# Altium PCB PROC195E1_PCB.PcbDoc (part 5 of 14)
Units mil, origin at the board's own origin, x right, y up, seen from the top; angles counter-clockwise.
Board outline 3110.24 x 2500 mil, 10 copper layers (Top Layer, L02_GND1, L03_SIG1, L04_GND2, L05_PWR1, L06_PWR2, L07_GND3, L08_SIG2, L09_GND4, Bottom Layer), stack 66.407 mil thick; 571 components, 538 nets, 6726 pads, 1286 vias.
Unrouted connection lines stored in the file: 4.
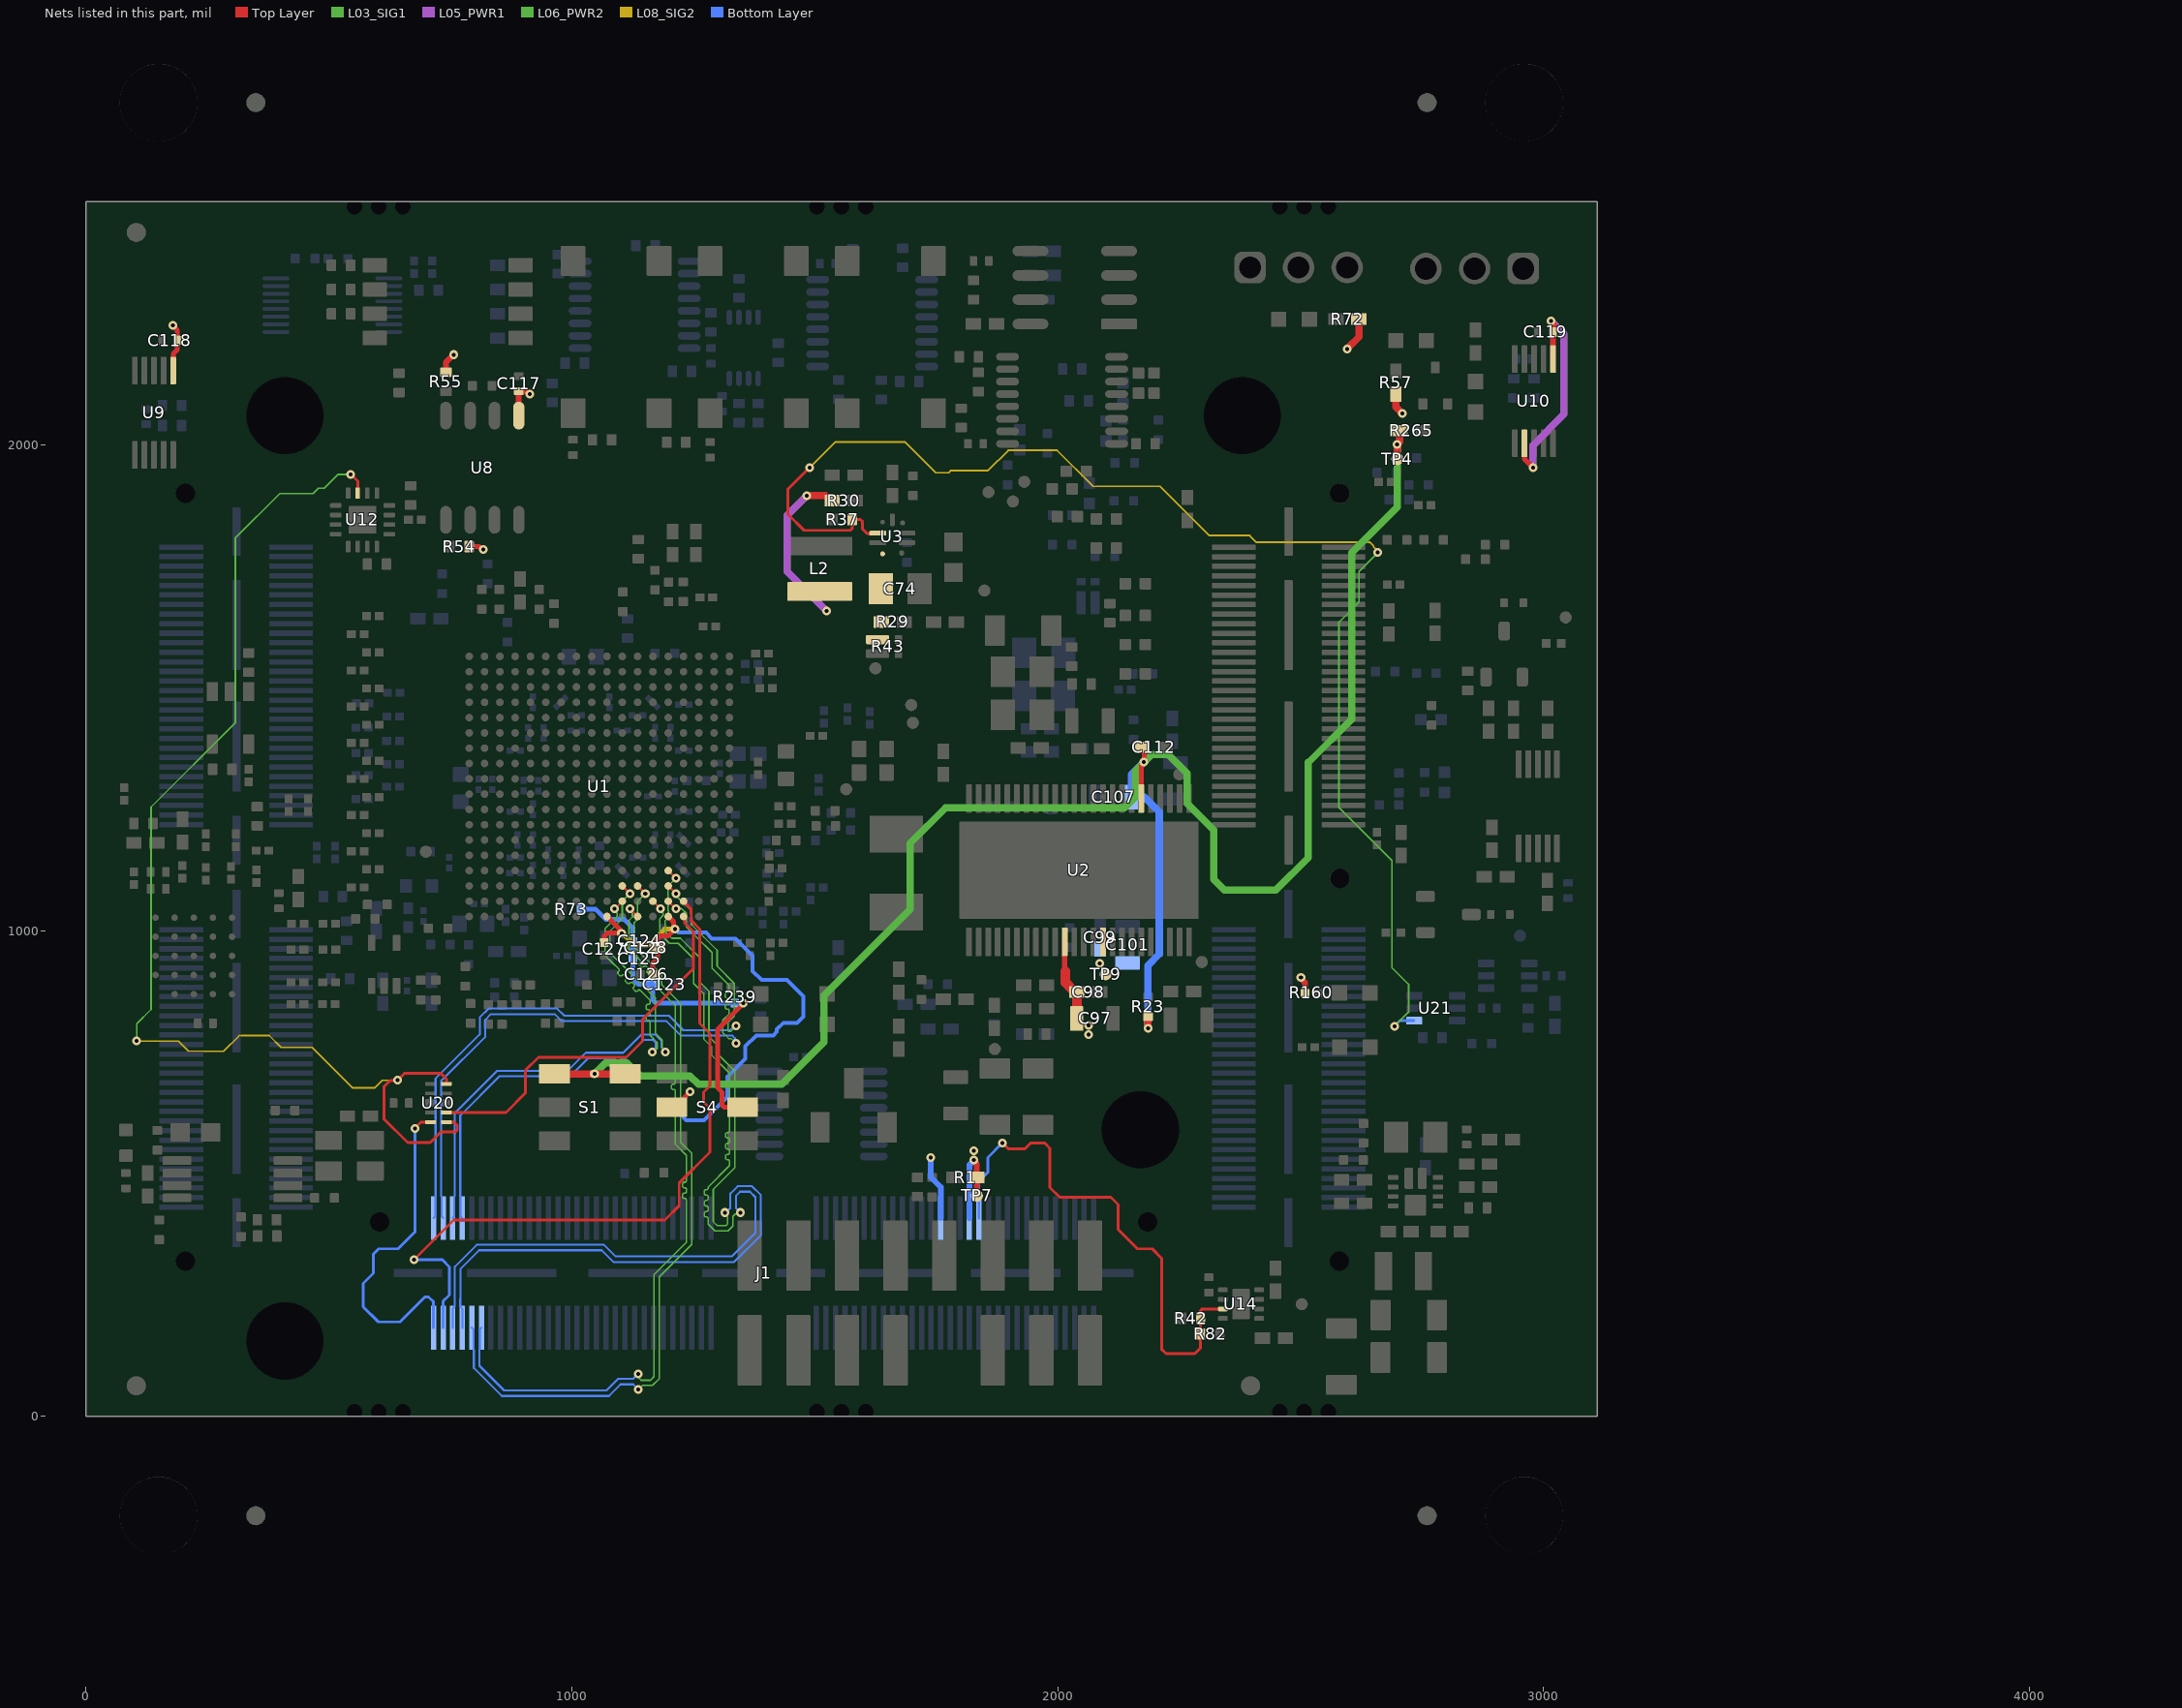
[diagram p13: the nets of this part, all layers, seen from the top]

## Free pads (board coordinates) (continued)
  round 2.5 on Mech16: 1(2331.73,1000.23) 1(2331.73,1006.23) 1(2331.73,1216.72) 1(2331.73,1222.72) 1(2331.73,1236.41) 1(2331.73,1242.41) 1(2331.73,1256.1) 1(2331.73,1262.1) 1(2331.73,1275.79) 1(2331.73,1281.79) 1(2331.73,1295.48) 1(2331.73,1301.48) 1(2331.73,1315.17) 1(2331.73,1321.17) 1(2331.73,1334.86) 1(2331.73,1340.86) 1(2331.73,1354.55) 1(2331.73,1360.55) 1(2331.73,1374.24) 1(2331.73,1380.24) 1(2331.73,1393.93) 1(2331.73,1399.93) 1(2331.73,1413.62) 1(2331.73,1419.62) 1(2331.73,1433.31) 1(2331.73,1439.31) 1(2331.73,1453) 1(2331.73,1459) 1(2331.73,1472.69) 1(2331.73,1478.69) 1(2331.73,1492.38) 1(2331.73,1498.38) 1(2331.73,1512.07) 1(2331.73,1518.07) 1(2331.73,1531.76) 1(2331.73,1537.76) 1(2331.73,1551.45) 1(2331.73,1557.45) 1(2331.73,1571.14) 1(2331.73,1577.14) 1(2331.73,1590.83) 1(2331.73,1596.83) 1(2331.73,1610.47) 1(2331.73,1610.52) 1(2331.73,1616.47) 1(2331.73,1616.52) 1(2331.73,1630.21) 1(2331.73,1636.21) 1(2331.73,1649.9) 1(2331.73,1655.9) 1(2331.73,1669.59) 1(2331.73,1675.59) 1(2331.73,1689.28) 1(2331.73,1695.28) 1(2331.73,1708.97) 1(2331.73,1714.97) 1(2331.73,1728.66) 1(2331.73,1734.66) 1(2331.73,1748.35) 1(2331.73,1754.35) 1(2331.73,1768.04) 1(2331.73,1774.04) 1(2331.73,1787.73) 1(2331.73,1793.73) 1(2331.73,1923.98) 1(2331.73,1923.98) 1(2345.96,314.7) 1(2345.96,314.7) 1(2345.96,314.7) 1(2345.96,1908.25) 1(2345.96,1908.25) 1(2345.96,1908.25) 1(2351.73,320.48) 1(2351.73,320.48) 1(2351.73,320.48) 1(2351.73,1902.48) 1(2351.73,1902.48) 1(2351.73,1902.48) 1(2541.73,320.48) 1(2541.73,320.48) 1(2541.73,320.48) 1(2541.73,1902.48) 1(2541.73,1902.48) 1(2541.73,1902.48) 1(2544.12,314.7) 1(2544.12,314.7) 1(2544.12,314.7) 1(2544.12,1908.25) 1(2544.12,1908.25) 1(2544.12,1908.25) 1(2547.71,306.98) 1(2547.71,306.98) 1(2596.73,375.48) 1(2596.73,375.48) 1(2596.73,375.48) 1(2596.73,1847.48) 1(2596.73,1847.48) 1(2596.73,1847.48) 1(2602.51,373.08) 1(2602.51,373.08) 1(2602.51,373.08) 1(2602.51,1849.87) 1(2602.51,1849.87) 1(2602.51,1849.87) 1(2608.73,306.98) 1(2608.73,306.98) 1(2608.73,368) 1(2608.73,368) 1(2616.73,298.98) 1(2616.73,298.98) 1(2616.73,429.22) 1(2616.73,435.22) 1(2616.73,448.91) 1(2616.73,454.91) 1(2616.73,468.6) 1(2616.73,474.6) 1(2616.73,488.29) 1(2616.73,494.29) 1(2616.73,507.98) 1(2616.73,513.98) 1(2616.73,527.67) 1(2616.73,533.67) 1(2616.73,547.36) 1(2616.73,553.36) 1(2616.73,567.05) 1(2616.73,573.05) 1(2616.73,586.74) 1(2616.73,592.74) 1(2616.73,606.43) 1(2616.73,612.43) 1(2616.73,626.12) 1(2616.73,632.12) 1(2616.73,645.81) 1(2616.73,651.81) 1(2616.73,665.5) 1(2616.73,671.5) 1(2616.73,685.19) 1(2616.73,691.19) 1(2616.73,704.88) 1(2616.73,710.88) 1(2616.73,724.57) 1(2616.73,730.57) 1(2616.73,744.26) 1(2616.73,750.26) 1(2616.73,763.95) 1(2616.73,769.95) 1(2616.73,783.64) 1(2616.73,789.64) 1(2616.73,803.33) 1(2616.73,809.33) 1(2616.73,823.02) 1(2616.73,829.02) 1(2616.73,842.71) 1(2616.73,848.71) 1(2616.73,862.4) 1(2616.73,868.4) 1(2616.73,882.09) 1(2616.73,888.09) 1(2616.73,901.78) 1(2616.73,907.78) 1(2616.73,921.47) 1(2616.73,927.47) 1(2616.73,941.16) 1(2616.73,947.16) 1(2616.73,960.85) 1(2616.73,966.85) 1(2616.73,980.54) 1(2616.73,986.54) 1(2616.73,1000.23) 1(2616.73,1006.23) 1(2616.73,1216.72) 1(2616.73,1222.72) 1(2616.73,1236.41) 1(2616.73,1242.41) 1(2616.73,1256.1) 1(2616.73,1262.1) 1(2616.73,1275.79) 1(2616.73,1281.79) 1(2616.73,1295.48) 1(2616.73,1301.48) 1(2616.73,1315.17) 1(2616.73,1321.17) 1(2616.73,1334.86) 1(2616.73,1340.86) 1(2616.73,1354.55) 1(2616.73,1360.55) 1(2616.73,1374.24) 1(2616.73,1380.24) 1(2616.73,1393.93) 1(2616.73,1399.93) 1(2616.73,1413.62) 1(2616.73,1419.62) 1(2616.73,1433.31) 1(2616.73,1439.31) 1(2616.73,1453) 1(2616.73,1459) 1(2616.73,1472.69) 1(2616.73,1478.69) 1(2616.73,1492.38) 1(2616.73,1498.38) 1(2616.73,1512.07) 1(2616.73,1518.07) 1(2616.73,1531.76) 1(2616.73,1537.76) 1(2616.73,1551.45) 1(2616.73,1557.45) 1(2616.73,1571.14) 1(2616.73,1577.14) 1(2616.73,1590.83) 1(2616.73,1596.83) 1(2616.73,1610.47) 1(2616.73,1610.52) 1(2616.73,1616.47) 1(2616.73,1616.52) 1(2616.73,1630.21) 1(2616.73,1636.21) 1(2616.73,1649.9) 1(2616.73,1655.9) 1(2616.73,1669.59) 1(2616.73,1675.59) 1(2616.73,1689.28) 1(2616.73,1695.28) 1(2616.73,1708.97) 1(2616.73,1714.97) 1(2616.73,1728.66) 1(2616.73,1734.66) 1(2616.73,1748.35) 1(2616.73,1754.35) 1(2616.73,1768.04) 1(2616.73,1774.04) 1(2616.73,1787.73) 1(2616.73,1793.73) 1(2616.73,1923.98) 1(2616.73,1923.98) 1(2621.73,429.22) 1(2621.73,429.22) 1(2621.73,435.22) 1(2621.73,435.22) 1(2621.73,448.91) 1(2621.73,448.91) 1(2621.73,454.91) 1(2621.73,454.91) 1(2621.73,468.6) 1(2621.73,468.6) 1(2621.73,474.6) 1(2621.73,474.6) 1(2621.73,488.29) 1(2621.73,488.29) 1(2621.73,494.29) 1(2621.73,494.29) 1(2621.73,507.98) 1(2621.73,507.98) 1(2621.73,513.98) 1(2621.73,513.98) 1(2621.73,527.67) 1(2621.73,527.67) 1(2621.73,533.67) 1(2621.73,533.67) 1(2621.73,547.36) 1(2621.73,547.36) 1(2621.73,553.36) 1(2621.73,553.36) 1(2621.73,567.05) 1(2621.73,567.05) 1(2621.73,573.05) 1(2621.73,573.05) 1(2621.73,586.74) 1(2621.73,586.74) 1(2621.73,592.74) 1(2621.73,592.74) 1(2621.73,606.43) 1(2621.73,606.43) 1(2621.73,612.43) 1(2621.73,612.43) 1(2621.73,626.12) 1(2621.73,626.12) 1(2621.73,632.12) 1(2621.73,632.12) 1(2621.73,645.81) 1(2621.73,645.81) 1(2621.73,651.81) 1(2621.73,651.81) 1(2621.73,665.5) 1(2621.73,665.5) 1(2621.73,671.5) 1(2621.73,671.5) 1(2621.73,685.19) 1(2621.73,685.19) 1(2621.73,691.19) 1(2621.73,691.19) 1(2621.73,704.88) 1(2621.73,704.88) 1(2621.73,710.88) 1(2621.73,710.88) 1(2621.73,724.57) 1(2621.73,724.57) 1(2621.73,730.57) 1(2621.73,730.57) 1(2621.73,744.26) 1(2621.73,744.26) 1(2621.73,750.26) 1(2621.73,750.26) 1(2621.73,763.95) 1(2621.73,763.95) 1(2621.73,769.95) 1(2621.73,769.95) 1(2621.73,783.64) 1(2621.73,783.64) 1(2621.73,789.64) 1(2621.73,789.64) 1(2621.73,803.33) 1(2621.73,803.33) 1(2621.73,809.33) 1(2621.73,809.33) 1(2621.73,823.02) 1(2621.73,823.02) 1(2621.73,829.02) 1(2621.73,829.02) 1(2621.73,842.71) 1(2621.73,842.71) 1(2621.73,848.71) 1(2621.73,848.71) 1(2621.73,862.4) 1(2621.73,862.4) 1(2621.73,868.4) 1(2621.73,868.4) 1(2621.73,882.09) 1(2621.73,882.09) 1(2621.73,888.09) 1(2621.73,888.09) 1(2621.73,901.78) 1(2621.73,901.78) 1(2621.73,907.78) 1(2621.73,907.78) 1(2621.73,921.47) 1(2621.73,921.47) 1(2621.73,927.47) 1(2621.73,927.47) 1(2621.73,941.16) 1(2621.73,941.16) 1(2621.73,947.16) 1(2621.73,947.16) 1(2621.73,960.85) 1(2621.73,960.85) 1(2621.73,966.85) 1(2621.73,966.85) 1(2621.73,980.54) 1(2621.73,980.54) 1(2621.73,986.54) 1(2621.73,986.54) 1(2621.73,1000.23) 1(2621.73,1000.23) 1(2621.73,1006.23) 1(2621.73,1006.23) 1(2621.73,1216.72) 1(2621.73,1216.72) 1(2621.73,1222.72) 1(2621.73,1222.72) 1(2621.73,1236.41) 1(2621.73,1236.41) 1(2621.73,1242.41) 1(2621.73,1242.41) 1(2621.73,1256.1) 1(2621.73,1256.1) 1(2621.73,1262.1) 1(2621.73,1262.1) 1(2621.73,1275.79) 1(2621.73,1275.79) 1(2621.73,1281.79) 1(2621.73,1281.79) 1(2621.73,1295.48) 1(2621.73,1295.48) 1(2621.73,1301.48) 1(2621.73,1301.48) 1(2621.73,1315.17) 1(2621.73,1315.17) 1(2621.73,1321.17) 1(2621.73,1321.17) 1(2621.73,1334.86) 1(2621.73,1334.86) 1(2621.73,1340.86) 1(2621.73,1340.86) 1(2621.73,1354.55) 1(2621.73,1354.55) 1(2621.73,1360.55) 1(2621.73,1360.55) 1(2621.73,1374.24) 1(2621.73,1374.24) 1(2621.73,1380.24) 1(2621.73,1380.24) 1(2621.73,1393.93) 1(2621.73,1393.93) 1(2621.73,1399.93) 1(2621.73,1399.93) 1(2621.73,1413.62) 1(2621.73,1413.62) 1(2621.73,1419.62) 1(2621.73,1419.62) 1(2621.73,1433.31) 1(2621.73,1433.31) 1(2621.73,1439.31) 1(2621.73,1439.31) 1(2621.73,1453) 1(2621.73,1453) 1(2621.73,1459) 1(2621.73,1459) 1(2621.73,1472.69) 1(2621.73,1472.69) 1(2621.73,1478.69) 1(2621.73,1478.69) 1(2621.73,1492.38) 1(2621.73,1492.38) 1(2621.73,1498.38) 1(2621.73,1498.38) 1(2621.73,1512.07) 1(2621.73,1512.07) 1(2621.73,1518.07) 1(2621.73,1518.07) 1(2621.73,1531.76) 1(2621.73,1531.76) 1(2621.73,1537.76) 1(2621.73,1537.76) 1(2621.73,1551.45) 1(2621.73,1551.45) 1(2621.73,1557.45) 1(2621.73,1557.45) 1(2621.73,1571.14) 1(2621.73,1571.14) 1(2621.73,1577.14) 1(2621.73,1577.14) 1(2621.73,1590.83) 1(2621.73,1590.83) 1(2621.73,1596.83) 1(2621.73,1596.83) 1(2621.73,1610.47) 1(2621.73,1610.47) 1(2621.73,1610.52) 1(2621.73,1610.52) 1(2621.73,1616.47) 1(2621.73,1616.47) 1(2621.73,1616.52) 1(2621.73,1616.52) 1(2621.73,1630.21) 1(2621.73,1630.21) 1(2621.73,1636.21) 1(2621.73,1636.21) 1(2621.73,1649.9) 1(2621.73,1649.9) 1(2621.73,1655.9) 1(2621.73,1655.9) 1(2621.73,1669.59) 1(2621.73,1669.59) 1(2621.73,1675.59) 1(2621.73,1675.59) 1(2621.73,1689.28) 1(2621.73,1689.28) 1(2621.73,1695.28) 1(2621.73,1695.28) 1(2621.73,1708.97) 1(2621.73,1708.97) 1(2621.73,1714.97) 1(2621.73,1714.97) 1(2621.73,1728.66) 1(2621.73,1728.66) 1(2621.73,1734.66) 1(2621.73,1734.66) 1(2621.73,1748.35) 1(2621.73,1748.35) 1(2621.73,1754.35) 1(2621.73,1754.35) 1(2621.73,1768.04) 1(2621.73,1768.04) 1(2621.73,1774.04) 1(2621.73,1774.04) 1(2621.73,1787.73) 1(2621.73,1787.73) 1(2621.73,1793.73) 1(2621.73,1793.73)
  round 3.94 on Mech16: 1(192.48,1023.39) 1(192.48,1196.61) 1(192.68,367.32) 1(192.68,367.32) 1(192.68,409.21) 1(192.68,1810.79) 1(192.68,1852.68) 1(192.68,1852.68) 1(237.52,322.48) 1(237.52,322.48) 1(237.52,1897.52) 1(237.52,1897.52) 1(364.13,322.48) 1(364.13,1897.52) 1(427.32,1810.79) 1(427.32,1897.6) 1(427.52,323.19) 1(427.52,410) 1(427.52,1023.39) 1(427.52,1196.61) 1(513.9,-174.26) 1(513.9,-174.26) 1(513.9,-144.74) 1(513.9,-114.22) 1(513.9,-102.41) 1(519.81,-174.26) 1(592.64,-169.34) 1(592.64,-157.53) 1(592.64,-114.22) 1(592.64,-102.41) 1(607.48,240.87) 1(607.48,367.48) 1(607.48,367.48) 1(607.48,1865.87) 1(607.48,1992.48) 1(607.48,1992.48) 1(608.19,177.48) 1(608.19,1802.48) 1(652.32,412.32) 1(652.32,412.32) 1(652.32,2037.32) 1(652.32,2037.32) 1(694.21,412.32) 1(694.21,2037.32) 1(695,177.48) 1(695,1802.48) 1(735.63,-173.39) 1(735.63,-173.39) 1(735.63,-143.86) 1(735.63,-113.35) 1(735.63,-101.53) 1(741.54,-173.39) 1(814.37,-168.46) 1(814.37,-156.65) 1(814.37,-113.35) 1(814.37,-101.53) 1(969.98,-176.52) 1(969.98,-176.52) 1(969.98,-146.99) 1(969.98,-116.48) 1(969.98,-104.67) 1(975.88,-176.52) 1(1048.72,-171.6) 1(1048.72,-159.79) 1(1048.72,-116.48) 1(1048.72,-104.67) 1(1308.39,177.48) 1(1308.39,412.52) 1(1308.39,1802.48) 1(1308.39,2037.52) 1(1481.61,177.48) 1(1481.61,412.52) 1(1481.61,1802.48) 1(1481.61,2037.52) 1(2095.79,177.68) 1(2095.79,412.32) 1(2095.79,1802.68) 1(2095.79,2037.32) 1(2126.37,75) 1(2137.68,412.32) 1(2137.68,412.32) 1(2137.68,2037.32) 1(2137.68,2037.32) 1(2182.52,240.87) 1(2182.52,367.48) 1(2182.52,367.48) 1(2182.52,1865.87) 1(2182.52,1992.48) 1(2182.52,1992.48) 1(2182.6,177.68) 1(2182.6,1802.68) 1(2233.63,75) 1(2357.48,1023.39) 1(2357.48,1196.61) 1(2357.48,1810) 1(2357.48,1896.81) 1(2357.68,322.4) 1(2357.68,409.21) 1(2366.37,-15) 1(2386.37,175) 1(2420.87,322.48) 1(2420.87,1897.52) 1(2473.63,-15) 1(2493.63,175) 1(2547.48,322.48) 1(2547.48,322.48) 1(2547.48,1897.52) 1(2547.48,1897.52) 1(2592.32,367.32) 1(2592.32,367.32) 1(2592.32,409.21) 1(2592.32,1810.79) 1(2592.32,1852.68) 1(2592.32,1852.68) 1(2592.52,1023.39) 1(2592.52,1196.61) 1(2835.35,1078.35) 1(2835.35,1121.65) 1(2835.35,1128.35) 1(2835.35,1171.65) 1(2906.21,1078.35) 1(2906.21,1121.65) 1(2906.21,1128.35) 1(2906.21,1171.65) 1(3027.15,606.09) 1(3027.15,610.81) 1(3027.15,610.81) 1(3027.15,1559.37) 1(3027.15,1564.09) 1(3027.15,1564.09) 1(3032.07,610.81) 1(3032.07,610.81) 1(3032.07,1564.09) 1(3032.07,1564.09) 1(3037.98,496.64) 1(3037.98,1449.92) 1(3069.48,496.64) 1(3069.48,1449.92) 1(3075.38,610.81) 1(3075.38,1564.09) 1(3481.37,1020) 1(3588.63,1020)
  round 3.5 on Mech16: 1(293.38,-174.89) 1(293.38,-174.89) 1(293.38,-133.89) 1(293.38,-133.89) 1(316.38,-174.89) 1(316.38,-133.89) 1(323.35,-108) 1(323.35,-108) 1(323.35,-85) 1(323.35,-35) 1(323.35,-12) 1(323.35,-12) 1(364.35,-108) 1(364.35,-108) 1(364.35,-85) 1(364.35,-35) 1(364.35,-12) 1(364.35,-12) 1(366.38,-174.89) 1(366.38,-133.89) 1(384.5,-108) 1(384.5,-108) 1(384.5,-85) 1(384.5,-35) 1(384.5,-12) 1(384.5,-12) 1(389.38,-174.89) 1(389.38,-174.89) 1(389.38,-133.89) 1(389.38,-133.89) 1(413.38,-180.5) 1(413.38,-180.5) 1(413.38,-139.5) 1(413.38,-139.5) 1(425.5,-108) 1(425.5,-108) 1(425.5,-85) 1(425.5,-35) 1(425.5,-12) 1(425.5,-12) 1(436.38,-180.5) 1(436.38,-139.5) 1(486.38,-180.5) 1(486.38,-139.5) 1(486.39,575.77) 1(486.39,575.77) 1(486.39,601.75) 1(486.39,669.75) 1(486.39,695.73) 1(486.39,695.73) 1(509.38,-180.5) 1(509.38,-180.5) 1(509.38,-139.5) 1(509.38,-139.5) 1(518.35,-29.69) 1(518.35,-29.69) 1(518.35,-6.69) 1(518.35,43.31) 1(518.35,66.31) 1(518.35,66.31) 1(540.86,575.77) 1(540.86,575.77) 1(540.86,601.75) 1(540.86,669.75) 1(540.86,695.73) 1(540.86,695.73) 1(553.35,575.77) 1(553.35,575.77) 1(553.35,601.75) 1(553.35,669.75) 1(553.35,695.73) 1(553.35,695.73) 1(559.35,-29.69) 1(559.35,-29.69) 1(559.35,-6.69) 1(559.35,43.31) 1(559.35,66.31) 1(559.35,66.31) 1(579.5,-29.69) 1(579.5,-29.69) 1(579.5,-6.69) 1(579.5,43.31) 1(579.5,66.31) 1(579.5,66.31) 1(607.82,575.77) 1(607.82,575.77) 1(607.82,601.75) 1(607.82,669.75) 1(607.82,695.73) 1(607.82,695.73) 1(618.02,-175.32) 1(618.02,-175.32) 1(618.02,-134.32) 1(618.02,-134.32) 1(620.5,-29.69) 1(620.5,-29.69) 1(620.5,-6.69) 1(620.5,43.31) 1(620.5,66.31) 1(620.5,66.31) 1(620.73,575.77) 1(620.73,575.77) 1(620.73,601.75) 1(620.73,669.75) 1(620.73,695.73) 1(620.73,695.73) 1(641.02,-175.32) 1(641.02,-134.32) 1(657.05,-42.68) 1(657.05,-42.68) 1(657.05,-19.68) 1(657.05,30.32) 1(657.05,53.32) 1(657.05,53.32) 1(675.19,575.77) 1(675.19,575.77) 1(675.19,601.75) 1(675.19,669.75) 1(675.19,695.73) 1(675.19,695.73) 1(688.17,575.77) 1(688.17,575.77) 1(688.17,601.75) 1(688.17,669.75) 1(688.17,695.73) 1(688.17,695.73) 1(691.02,-175.32) 1(691.02,-134.32) 1(698.05,-42.68) 1(698.05,-42.68) 1(698.05,-19.68) 1(698.05,30.32) 1(698.05,53.32) 1(698.05,53.32) 1(714.02,-175.32) 1(714.02,-175.32) 1(714.02,-134.32) 1(714.02,-134.32) 1(718.2,-42.68) 1(718.2,-42.68) 1(718.2,-19.68) 1(718.2,30.32) 1(718.2,53.32) 1(718.2,53.32) 1(742.64,575.77) 1(742.64,575.77) 1(742.64,601.75) 1(742.64,669.75) 1(742.64,695.73) 1(742.64,695.73) 1(755.61,575.77) 1(755.61,575.77) 1(755.61,601.75) 1(755.61,669.75) 1(755.61,695.73) 1(755.61,695.73) 1(759.2,-42.68) 1(759.2,-42.68) 1(759.2,-19.68) 1(759.2,30.32) 1(759.2,53.32) 1(759.2,53.32) 1(810.08,575.77) 1(810.08,575.77) 1(810.08,601.75) 1(810.08,669.75) 1(810.08,695.73) 1(810.08,695.73) 1(823.05,575.77) 1(823.05,575.77) 1(823.05,601.75) 1(823.05,669.75) 1(823.05,695.73) 1(823.05,695.73) 1(838.35,-32.53) 1(838.35,-32.53) 1(838.35,-9.53) 1(838.35,40.47) 1(838.35,63.47) 1(838.35,63.47) 1(877.52,575.77) 1(877.52,575.77) 1(877.52,601.75) 1(877.52,669.75) 1(877.52,695.73) 1(877.52,695.73) 1(879.35,-32.53) 1(879.35,-32.53) 1(879.35,-9.53) 1(879.35,40.47) 1(879.35,63.47) 1(879.35,63.47) 1(890.5,575.77) 1(890.5,575.77) 1(890.5,601.75) 1(890.5,669.75) 1(890.5,695.73) 1(890.5,695.73) 1(899.5,-32.53) 1(899.5,-32.53) 1(899.5,-9.53) 1(899.5,40.47) 1(899.5,63.47) 1(899.5,63.47) 1(920.91,-180.47) 1(920.91,-180.47) 1(920.91,-157.47) 1(920.91,-107.47) 1(920.91,-84.47) 1(920.91,-84.47) 1(940.5,-32.53) 1(940.5,-32.53) 1(940.5,-9.53) 1(940.5,40.47) 1(940.5,63.47) 1(940.5,63.47) 1(944.96,575.77) 1(944.96,575.77) 1(944.96,601.75) 1(944.96,669.75) 1(944.96,695.73) 1(944.96,695.73) 1(957.94,575.77) 1(957.94,575.77) 1(957.94,601.75) 1(957.94,669.75) 1(957.94,695.73) 1(957.94,695.73) 1(961.91,-180.47) 1(961.91,-180.47) 1(961.91,-157.47) 1(961.91,-107.47) 1(961.91,-84.47) 1(961.91,-84.47) 1(1012.4,575.77) 1(1012.4,575.77) 1(1012.4,601.75) 1(1012.4,669.75) 1(1012.4,695.73) 1(1012.4,695.73) 1(1025.38,575.77) 1(1025.38,575.77) 1(1025.38,601.75) 1(1025.38,669.75) 1(1025.38,695.73) 1(1025.38,695.73) 1(1026.54,-32.68) 1(1026.54,-32.68) 1(1026.54,-9.68) 1(1026.54,40.32) 1(1026.54,63.32) 1(1026.54,63.32) 1(1067.54,-32.68) 1(1067.54,-32.68) 1(1067.54,-9.68) 1(1067.54,40.32) 1(1067.54,63.32) 1(1067.54,63.32) 1(1079.84,575.77) 1(1079.84,575.77) 1(1079.84,601.75) 1(1079.84,669.75) 1(1079.84,695.73) 1(1079.84,695.73) 1(1087.69,-32.68) 1(1087.69,-32.68) 1(1087.69,-9.68) 1(1087.69,40.32) 1(1087.69,63.32) 1(1087.69,63.32) 1(1092.82,575.77) 1(1092.82,575.77) 1(1092.82,601.75) 1(1092.82,669.75) 1(1092.82,695.73) 1(1092.82,695.73) 1(1106.84,-121.34) 1(1106.84,-121.34) 1(1106.84,-80.34) 1(1106.84,-80.34) 1(1128.69,-32.68) 1(1128.69,-32.68) 1(1128.69,-9.68) 1(1128.69,40.32) 1(1128.69,63.32) 1(1128.69,63.32) 1(1129.84,-121.34) 1(1129.84,-80.34) 1(1147.29,575.77) 1(1147.29,575.77) 1(1147.29,601.75) 1(1147.29,669.75) 1(1147.29,695.73) 1(1147.29,695.73) 1(1160.26,575.77) 1(1160.26,575.77) 1(1160.26,601.75) 1(1160.26,669.75) 1(1160.26,695.73) 1(1160.26,695.73) 1(1169.8,-23.29) 1(1169.8,-23.29) 1(1169.8,-0.29) 1(1169.8,49.71) 1(1169.8,72.71) 1(1169.8,72.71) 1(1179.84,-121.34) 1(1179.84,-80.34) 1(1202.84,-121.34) 1(1202.84,-121.34) 1(1202.84,-80.34) 1(1202.84,-80.34) 1(1210.8,-23.29) 1(1210.8,-23.29) 1(1210.8,-0.29) 1(1210.8,49.71) 1(1210.8,72.71) 1(1210.8,72.71) 1(1214.73,575.77) 1(1214.73,575.77) 1(1214.73,601.75) 1(1214.73,669.75) 1(1214.73,695.73) 1(1214.73,695.73) 1(1227.7,575.77) 1(1227.7,575.77) 1(1227.7,601.75) 1(1227.7,669.75) 1(1227.7,695.73) 1(1227.7,695.73) 1(1230.95,-23.29) 1(1230.95,-23.29) 1(1230.95,-0.29) 1(1230.95,49.71) 1(1230.95,72.71) 1(1230.95,72.71) 1(1271.95,-23.29) 1(1271.95,-23.29) 1(1271.95,-0.29) 1(1271.95,49.71) 1(1271.95,72.71) 1(1271.95,72.71) 1(1282.17,575.77) 1(1282.17,575.77) 1(1282.17,601.75) 1(1282.17,669.75) 1(1282.17,695.73) 1(1282.17,695.73) 1(1751,515.5) 1(1751,515.5) 1(1751,556.5) 1(1751,556.5) 1(1774,515.5) 1(1774,556.5) 1(1824,515.5) 1(1824,556.5) 1(1847,515.5) 1(1847,515.5) 1(1847,556.5) 1(1847,556.5) 1(1885.66,463.36) 1(1885.66,463.36) 1(1885.66,504.36) 1(1885.66,504.36) 1(1885.66,515.15) 1(1885.66,515.15) 1(1885.66,556.15) 1(1885.66,556.15) 1(1908.66,463.36) 1(1908.66,504.36) 1(1908.66,515.15) 1(1908.66,556.15) 1(1958.66,463.36) 1(1958.66,504.36) 1(1958.66,515.15) 1(1958.66,556.15) 1(1981.66,463.36) 1(1981.66,463.36) 1(1981.66,504.36) 1(1981.66,504.36) 1(1981.66,515.15) 1(1981.66,515.15) 1(1981.66,556.15) 1(1981.66,556.15) 1(2212.87,-166.04) 1(2212.87,-166.04) 1(2212.87,-125.04) 1(2212.87,-125.04) 1(2212.87,-116.93) 1(2212.87,-116.93) 1(2212.87,-75.93) 1(2212.87,-75.93) 1(2235.87,-166.04) 1(2235.87,-125.04) 1(2235.87,-116.93) 1(2235.87,-75.93) 1(2285.87,-166.04) 1(2285.87,-125.04) 1(2285.87,-116.93) 1(2285.87,-75.93) 1(2308.87,-166.04) 1(2308.87,-166.04) 1(2308.87,-125.04) 1(2308.87,-125.04) 1(2308.87,-116.93) 1(2308.87,-116.93) 1(2308.87,-75.93) 1(2308.87,-75.93) 1(2319.02,-177.46) 1(2319.02,-177.46) 1(2319.02,-136.46) 1(2319.02,-136.46) 1(2319.02,-127.87) 1(2319.02,-127.87) 1(2319.02,-86.87) 1(2319.02,-86.87) 1(2342.02,-177.46) 1(2342.02,-136.46) 1(2342.02,-127.87) 1(2342.02,-86.87) 1(2392.02,-177.46) 1(2392.02,-136.46) 1(2392.02,-127.87) 1(2392.02,-86.87) 1(2415.02,-177.46) 1(2415.02,-177.46) 1(2415.02,-136.46) 1(2415.02,-136.46) 1(2415.02,-127.87) 1(2415.02,-127.87) 1(2415.02,-86.87) 1(2415.02,-86.87) 1(2677.97,724.97) 1(2677.97,724.97) 1(2677.97,747.97) 1(2677.97,797.97) 1(2677.97,820.97) 1(2677.97,820.97) 1(2677.97,837.22) 1(2677.97,837.22) 1(2677.97,860.22) 1(2677.97,910.22) 1(2677.97,933.22) 1(2677.97,933.22) 1(2677.97,1678.25) 1(2677.97,1678.25) 1(2677.97,1701.25) 1(2677.97,1751.25) 1(2677.97,1774.25) 1(2677.97,1774.25) 1(2677.97,1790.5) 1(2677.97,1790.5) 1(2677.97,1813.5) 1(2677.97,1863.5) 1(2677.97,1886.5) 1(2677.97,1886.5) 1(2718.97,724.97) 1(2718.97,724.97) 1(2718.97,747.97) 1(2718.97,797.97) 1(2718.97,820.97) 1(2718.97,820.97) 1(2718.97,837.22) 1(2718.97,837.22) 1(2718.97,860.22) 1(2718.97,910.22) 1(2718.97,933.22) 1(2718.97,933.22) 1(2718.97,1678.25) 1(2718.97,1678.25) 1(2718.97,1701.25) 1(2718.97,1751.25) 1(2718.97,1774.25) 1(2718.97,1774.25) 1(2718.97,1790.5) 1(2718.97,1790.5) 1(2718.97,1813.5) 1(2718.97,1863.5) 1(2718.97,1886.5) 1(2718.97,1886.5) 1(2737.97,724.97) 1(2737.97,724.97) 1(2737.97,747.97) 1(2737.97,797.97) 1(2737.97,820.97) 1(2737.97,820.97) 1(2737.97,837.22) 1(2737.97,837.22) 1(2737.97,860.22) 1(2737.97,910.22) 1(2737.97,933.22) 1(2737.97,933.22) 1(2737.97,1678.25) 1(2737.97,1678.25) 1(2737.97,1701.25) 1(2737.97,1751.25) 1(2737.97,1774.25) 1(2737.97,1774.25) 1(2737.97,1790.5) 1(2737.97,1790.5) 1(2737.97,1813.5) 1(2737.97,1863.5) 1(2737.97,1886.5) 1(2737.97,1886.5) 1(2759.29,263.35) 1(2759.29,263.35) 1(2759.29,286.35) 1(2759.29,336.35) 1(2759.29,359.35) 1(2759.29,359.35) 1(2759.29,1216.63) 1(2759.29,1216.63) 1(2759.29,1239.63) 1(2759.29,1289.63) 1(2759.29,1312.63) 1(2759.29,1312.63) 1(2778.97,724.97) 1(2778.97,724.97) 1(2778.97,747.97) 1(2778.97,797.97) 1(2778.97,820.97) 1(2778.97,820.97) 1(2778.97,837.22) 1(2778.97,837.22) 1(2778.97,860.22) 1(2778.97,910.22) 1(2778.97,933.22) 1(2778.97,933.22) 1(2778.97,1678.25) 1(2778.97,1678.25) 1(2778.97,1701.25) 1(2778.97,1751.25) 1(2778.97,1774.25) 1(2778.97,1774.25) 1(2778.97,1790.5) 1(2778.97,1790.5) 1(2778.97,1813.5) 1(2778.97,1863.5) 1(2778.97,1886.5) 1(2778.97,1886.5) 1(2797.97,724.97) 1(2797.97,724.97) 1(2797.97,747.97) 1(2797.97,797.97) 1(2797.97,820.97) 1(2797.97,820.97) 1(2797.97,837.22) 1(2797.97,837.22) 1(2797.97,860.22) 1(2797.97,910.22) 1(2797.97,933.22) 1(2797.97,933.22) 1(2797.97,1678.25) 1(2797.97,1678.25) 1(2797.97,1701.25) 1(2797.97,1751.25) 1(2797.97,1774.25) 1(2797.97,1774.25) 1(2797.97,1790.5) 1(2797.97,1790.5) 1(2797.97,1813.5) 1(2797.97,1863.5) 1(2797.97,1886.5) 1(2797.97,1886.5) 1(2800.29,263.35) 1(2800.29,263.35) 1(2800.29,286.35) 1(2800.29,336.35) 1(2800.29,359.35) 1(2800.29,359.35) 1(2800.29,1216.63) 1(2800.29,1216.63) 1(2800.29,1239.63) 1(2800.29,1289.63) 1(2800.29,1312.63) 1(2800.29,1312.63) 1(2805.02,992.8) 1(2805.02,992.8) 1(2805.02,1047.27) 1(2805.02,1047.27) 1(2816.3,263.35) 1(2816.3,263.35) 1(2816.3,286.35) 1(2816.3,336.35) 1(2816.3,359.35) 1(2816.3,359.35) 1(2816.3,1216.63) 1(2816.3,1216.63) 1(2816.3,1239.63) 1(2816.3,1289.63) 1(2816.3,1312.63) 1(2816.3,1312.63) 1(2831,992.8) 1(2831,1047.27) 1(2838.97,724.97) 1(2838.97,724.97) 1(2838.97,747.97) 1(2838.97,797.97) 1(2838.97,820.97) 1(2838.97,820.97) 1(2838.97,837.22) 1(2838.97,837.22) 1(2838.97,860.22) 1(2838.97,910.22) 1(2838.97,933.22) 1(2838.97,933.22) 1(2838.97,1678.25) 1(2838.97,1678.25) 1(2838.97,1701.25) 1(2838.97,1751.25) 1(2838.97,1774.25) 1(2838.97,1774.25) 1(2838.97,1790.5) 1(2838.97,1790.5) 1(2838.97,1813.5) 1(2838.97,1863.5) 1(2838.97,1886.5) 1(2838.97,1886.5) 1(2857.3,263.35) 1(2857.3,263.35) 1(2857.3,286.35) 1(2857.3,336.35) 1(2857.3,359.35) 1(2857.3,359.35) 1(2857.3,1216.63) 1(2857.3,1216.63) 1(2857.3,1239.63) 1(2857.3,1289.63) 1(2857.3,1312.63) 1(2857.3,1312.63) 1(2857.97,724.97) 1(2857.97,724.97) 1(2857.97,747.97) 1(2857.97,797.97) 1(2857.97,820.97) 1(2857.97,820.97) 1(2857.97,837.22) 1(2857.97,837.22) 1(2857.97,860.22) 1(2857.97,910.22) 1(2857.97,933.22) 1(2857.97,933.22) 1(2857.97,1678.25) 1(2857.97,1678.25) 1(2857.97,1701.25) 1(2857.97,1751.25) 1(2857.97,1774.25) 1(2857.97,1774.25) 1(2857.97,1790.5) 1(2857.97,1790.5) 1(2857.97,1813.5) 1(2857.97,1863.5) 1(2857.97,1886.5) 1(2857.97,1886.5) 1(2870.02,263.35) 1(2870.02,263.35) 1(2870.02,286.35) 1(2870.02,336.35) 1(2870.02,359.35) 1(2870.02,359.35) 1(2870.02,1216.63) 1(2870.02,1216.63) 1(2870.02,1239.63) 1(2870.02,1289.63) 1(2870.02,1312.63) 1(2870.02,1312.63) 1(2898.97,724.97) 1(2898.97,724.97) 1(2898.97,747.97) 1(2898.97,797.97) 1(2898.97,820.97) 1(2898.97,820.97) 1(2898.97,837.22) 1(2898.97,837.22) 1(2898.97,860.22) 1(2898.97,910.22) 1(2898.97,933.22) 1(2898.97,933.22) 1(2898.97,1678.25) 1(2898.97,1678.25) 1(2898.97,1701.25) 1(2898.97,1751.25) 1(2898.97,1774.25) 1(2898.97,1774.25) 1(2898.97,1790.5) 1(2898.97,1790.5) 1(2898.97,1813.5) 1(2898.97,1863.5) 1(2898.97,1886.5) 1(2898.97,1886.5) 1(2899,992.8) 1(2899,1047.27) 1(2911.02,263.35) 1(2911.02,263.35) 1(2911.02,286.35) 1(2911.02,336.35) 1(2911.02,359.35) 1(2911.02,359.35) 1(2911.02,1216.63) 1(2911.02,1216.63) 1(2911.02,1239.63) 1(2911.02,1289.63) 1(2911.02,1312.63) 1(2911.02,1312.63) 1(2917.84,263.35) 1(2917.84,263.35) 1(2917.84,286.35) 1(2917.84,336.35) 1(2917.84,359.35) 1(2917.84,359.35) 1(2917.84,1216.63) 1(2917.84,1216.63) 1(2917.84,1239.63) 1(2917.84,1289.63) 1(2917.84,1312.63) 1(2917.84,1312.63) 1(2917.97,724.97) 1(2917.97,724.97) 1(2917.97,747.97) 1(2917.97,797.97) 1(2917.97,820.97) 1(2917.97,820.97) 1(2917.97,1678.25) 1(2917.97,1678.25) 1(2917.97,1701.25) 1(2917.97,1751.25) 1(2917.97,1774.25) 1(2917.97,1774.25) 1(2919.87,1129.5) 1(2919.87,1129.5) 1(2919.87,1170.5) 1(2919.87,1170.5) 1(2921.83,1079.5) 1(2921.83,1079.5) 1(2921.83,1120.5) 1(2921.83,1120.5) 1(2922,661.22) 1(2922,661.22) 1(2922,702.22) 1(2922,702.22) 1(2922,1614.5) 1(2922,1614.5) 1(2922,1655.5) 1(2922,1655.5) 1(2924.98,992.8) 1(2924.98,992.8) 1(2924.98,1047.27) 1(2924.98,1047.27) 1(2942.87,1129.5) 1(2942.87,1170.5) 1(2944.83,1079.5) 1(2944.83,1120.5) 1(2945,661.22) 1(2945,702.22) 1(2945,1614.5) 1(2945,1655.5) 1(2958.84,263.35) 1(2958.84,263.35) 1(2958.84,286.35) 1(2958.84,336.35) 1(2958.84,359.35) 1(2958.84,359.35) 1(2958.84,1216.63) 1(2958.84,1216.63) 1(2958.84,1239.63) 1(2958.84,1289.63) 1(2958.84,1312.63) 1(2958.84,1312.63) 1(2958.97,724.97) 1(2958.97,724.97) 1(2958.97,747.97) 1(2958.97,797.97) 1(2958.97,820.97) 1(2958.97,820.97) 1(2958.97,1678.25) 1(2958.97,1678.25) 1(2958.97,1701.25) 1(2958.97,1751.25) 1(2958.97,1774.25) 1(2958.97,1774.25) 1(2963.01,1399.75) 1(2963.01,1399.75) 1(2963.01,1440.75) 1(2963.01,1440.75) 1(2963.28,1334.75) 1(2963.28,1334.75) 1(2963.28,1389.21) 1(2963.28,1389.21) 1(2965.98,1204.03) 1(2965.98,1204.03) 1(2965.98,1230.02) 1(2965.98,1298.02) 1(2965.98,1324) 1(2965.98,1324) 1(2966.9,355.46) 1(2966.9,355.46) 1(2966.9,409.93) 1(2966.9,409.93) 1(2967.14,234.87) 1(2967.14,234.87) 1(2967.14,260.85) 1(2967.14,328.85) 1(2967.14,354.83) 1(2967.14,354.83) 1(2973.62,416.5) 1(2973.62,416.5) 1(2973.62,457.5) 1(2973.62,457.5) 1(2986.01,1399.75) 1(2986.01,1440.75) 1(2989.26,1334.75) 1(2989.26,1389.21) 1(2992.87,1129.5) 1(2992.87,1170.5) 1(2992.88,355.46) 1(2992.88,409.93) 1(2994.83,1079.5) 1(2994.83,1120.5) 1(2995,661.22) 1(2995,702.22) 1(2995,1614.5) 1(2995,1655.5) 1(2996.62,416.5) 1(2996.62,457.5) 1(3015.87,1129.5) 1(3015.87,1129.5) 1(3015.87,1170.5) 1(3015.87,1170.5) 1(3017.83,1079.5) 1(3017.83,1079.5) 1(3017.83,1120.5) 1(3017.83,1120.5) 1(3018,661.22) 1(3018,661.22) 1(3018,702.22) 1(3018,702.22) 1(3018,1614.5) 1(3018,1614.5) 1(3018,1655.5) 1(3018,1655.5) 1(3020.44,1204.03) 1(3020.44,1204.03) 1(3020.44,1230.02) 1(3020.44,1298.02) 1(3020.44,1324) 1(3020.44,1324) 1(3021.6,234.87) 1(3021.6,234.87) 1(3021.6,260.85) 1(3021.6,328.85) 1(3021.6,354.83) 1(3021.6,354.83) 1(3036.01,1399.75) 1(3036.01,1440.75) 1(3046.62,416.5) 1(3046.62,457.5) 1(3057.26,1334.75) 1(3057.26,1389.21) 1(3059.01,1399.75) 1(3059.01,1399.75) 1(3059.01,1440.75) 1(3059.01,1440.75) 1(3060.88,355.46) 1(3060.88,409.93) 1(3069.62,416.5) 1(3069.62,416.5) 1(3069.62,457.5) 1(3069.62,457.5) 1(3083.24,1334.75) 1(3083.24,1334.75) 1(3083.24,1389.21) 1(3083.24,1389.21) 1(3086.86,355.46) 1(3086.86,355.46) 1(3086.86,409.93) 1(3086.86,409.93)
  round 25 on Mech16: 1(339.95,-458.97) 1(339.95,-458.97) 1(339.95,-222.97) 1(1262.06,-458.97) 1(1262.06,-458.97) 1(1262.06,-261.97) 1(1262.06,-261.97) 1(1356.06,-458.97) 1(1356.06,-458.97) 1(1356.06,-261.97) 1(1356.06,-261.97) 1(2404.95,-458.97) 1(2404.95,-458.97) 1(2404.95,-222.97) 1(3153.26,-454.97) 1(3153.26,-454.97) 1(3153.26,-298.09) 1(4148.54,-454.97) 1(4148.54,-454.97) 1(4148.54,-222.87)
  round 10 on Mech16: 1(517,149.76) 1(517,149.76) 1(517,482.84) 1(522.16,488) 1(535.92,130.84) 1(535.92,130.84) 1(575,488) 1(575,488) 1(1786,488) 1(1998,484) 1(2150,484) 1(2150,484) 1(2201.84,130.84) 1(2201.84,130.84) 1(2215,144) 1(2215,144) 1(2215,419) 1(2215,419)
  round 2.95 on Mech16: 1(733.45,1236.85) 1(733.45,1236.85) 1(733.45,1278.19) 1(733.45,1278.19) 1(755.1,1236.85) 1(755.1,1236.85) 1(755.1,1278.19) 1(755.1,1278.19) 1(972.18,1311.88) 1(972.18,1311.88) 1(972.18,1333.53) 1(972.18,1333.53) 1(1013.51,1311.88) 1(1013.51,1311.88) 1(1013.51,1333.53) 1(1013.51,1333.53) 1(1163.31,1557.21) 1(1163.31,1557.21) 1(1163.31,1598.54) 1(1163.31,1598.54) 1(1184.97,1557.21) 1(1184.97,1557.21) 1(1184.97,1598.54) 1(1184.97,1598.54) 1(1574.33,1299.17) 1(1574.33,1299.17) 1(1574.33,1320.83) 1(1574.33,1320.83) 1(1615.67,1299.17) 1(1615.67,1299.17) 1(1615.67,1320.83) 1(1615.67,1320.83) 1(1683.38,496.22) 1(1683.38,496.22) 1(1683.38,523.78) 1(1683.38,523.78) 1(1730.62,496.22) 1(1730.62,496.22) 1(1730.62,523.78) 1(1730.62,523.78) 1(1746.22,1523.38) 1(1746.22,1523.38) 1(1746.22,1570.62) 1(1746.22,1570.62) 1(1773.78,1523.38) 1(1773.78,1523.38) 1(1773.78,1570.62) 1(1773.78,1570.62) 1(1901.13,1089.03) 1(1901.13,1089.03) 1(1901.13,1116.59) 1(1901.13,1116.59) 1(1902.5,1138.22) 1(1902.5,1138.22) 1(1902.5,1165.78) 1(1902.5,1165.78) 1(1948.38,1089.03) 1(1948.38,1089.03) 1(1948.38,1116.59) 1(1948.38,1116.59) 1(1949.75,1138.22) 1(1949.75,1138.22) 1(1949.75,1165.78) 1(1949.75,1165.78) 1(2023.55,1700.93) 1(2023.55,1700.93) 1(2023.55,1728.49) 1(2023.55,1728.49) 1(2028.38,1142.22) 1(2028.38,1142.22) 1(2028.38,1169.78) 1(2028.38,1169.78) 1(2070.79,1700.93) 1(2070.79,1700.93) 1(2070.79,1728.49) 1(2070.79,1728.49) 1(2075.62,1142.22) 1(2075.62,1142.22) 1(2075.62,1169.78) 1(2075.62,1169.78) 1(2111.22,1089.38) 1(2111.22,1089.38) 1(2111.22,1136.62) 1(2111.22,1136.62) 1(2111.22,1691.38) 1(2111.22,1691.38) 1(2111.22,1738.62) 1(2111.22,1738.62) 1(2138.78,1089.38) 1(2138.78,1089.38) 1(2138.78,1136.62) 1(2138.78,1136.62) 1(2138.78,1691.38) 1(2138.78,1691.38) 1(2138.78,1738.62) 1(2138.78,1738.62) 1(2666.49,1310.01) 1(2666.49,1365.13) 1(2668.77,304.04) 1(2668.77,345.38) 1(2703.38,1257.4) 1(2703.38,1298.74) 1(2704,320) 1(2704,329) 1(2707.83,1310.01) 1(2707.83,1365.13) 1(2723.88,329) 1(2724,321) 1(2726.57,433.65) 1(2726.57,433.65) 1(2726.57,445.46) 1(2726.57,622.62) 1(2726.57,634.43) 1(2726.57,634.43) 1(2726.57,1386.93) 1(2726.57,1386.93) 1(2726.57,1398.74) 1(2726.57,1575.9) 1(2726.57,1587.71) 1(2726.57,1587.71) 1(2738.38,433.65) 1(2738.38,634.43) 1(2738.38,1386.93) 1(2738.38,1587.71) 1(2758.5,304.12) 1(2758.5,345.46) 1(2758.5,1257.4) 1(2758.5,1298.74) 1(2915.54,433.65) 1(2915.54,634.43) 1(2915.54,1386.93) 1(2915.54,1587.71) 1(2927.35,433.65) 1(2927.35,433.65) 1(2927.35,445.46) 1(2927.35,622.62) 1(2927.35,634.43) 1(2927.35,634.43) 1(2927.35,1386.93) 1(2927.35,1386.93) 1(2927.35,1398.74) 1(2927.35,1575.9) 1(2927.35,1587.71) 1(2927.35,1587.71) 1(3027.44,679.33) 1(3027.44,720.67) 1(3043.39,1578.56) 1(3043.39,1633.68) 1(3082.56,679.33) 1(3082.56,720.67) 1(3084.73,1578.56) 1(3084.73,1633.68) 1(3235.46,2120.87) 1(3235.46,2120.87) 1(3235.46,2225.99) 1(3235.46,2225.99) 1(4050.42,2120.87) 1(4050.42,2120.87) 1(4050.42,2225.99) 1(4050.42,2225.99)
  round 0.5 on Mech16: 1(1828.82,1910.59) 1(1941.03,1910.59)
  round 107.26 on Mech16: 1(2180,75) 1(2420,-15) 1(2440,175) 1(3535,1020)
  round 4.92 on Mech16: 1(2950.98,465.14) 1(2950.98,1418.42) 1(2960.82,465.14) 1(2960.82,1418.42) 1(4040.58,2064.38) 1(4050.42,2064.38)
  round 9.84 on Mech16: 1(2955.9,465.14) 1(2955.9,1418.42) 1(4045.5,2064.38)
  round 160 hole 160 unplated: ""(150,2704.34) ""(150,-204.34) ""(2960.24,2704.34) ""(2960.24,-204.34)

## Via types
v1: diameter 18, hole 8, Top Layer to Bottom Layer, tented both sides, 1226 vias
v2: diameter 19.68, hole 7.87, Top Layer to Bottom Layer, tented top, 54 vias
v3: diameter 19.68, hole 7.87, Top Layer to Bottom Layer, 4 vias
v4: diameter 19.68, hole 7.87, Top Layer to Bottom Layer, tented both sides, 2 vias

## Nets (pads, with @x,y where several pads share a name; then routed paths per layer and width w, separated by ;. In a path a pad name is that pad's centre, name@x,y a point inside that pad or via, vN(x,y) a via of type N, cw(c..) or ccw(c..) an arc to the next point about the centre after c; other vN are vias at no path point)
1V8_LDO4: C107.1 C112.1 R23.1 R265.1 S1.1 S1.4 TP4.1 U2.30 | length 4058.9
  Top Layer w10: U2.30@2171.97,1271.95 2171.97,1339.38 2177.11,1344.51 v1(2177.11,1346.68) ; C112.1@2173.59,1377.5 2178.08,1373 2178.08,1351.03 v1@2176.4,1349.34
  Top Layer w15: S1.1@964.43,705.22 964.73,704.92 1046.52,704.92 v1(1046.74,705.14) ; v1@1045.36,704.92 1045.62,705.18 S1.4@1110.09,705.22 S1.4@1110.09,705.22 ; v1(2185.76,798.68) 2185.85,798.77 2185.85,822.86 R23.1@2185.94,822.95 ; v1(2698.65,2000.96) 2698.94,2000.68 2698.94,1970.81 TP4.1@2699.22,1970.52 ; v1@2699.65,2000.53 2700.09,2000.96 2700.09,2001.78 2704.27,2005.96 R265.1@2704.27,2028.96
  L06_PWR2 w15: v1(1046.74,705.14) 1069.72,728.12 1113.62,728.12 1140.94,700.79 1243.4,700.79 1260.77,683.43 1431.95,683.43 1519.13,770.61 1519.13,866.21 1696.88,1043.96 1696.88,1180.25 1769.65,1253.02 2137.53,1253.02 2159.35,1274.84 2159.35,1328.11 2177.11,1345.86 v1(2177.11,1346.68) ; v1@2177.8,1347.94 2178.49,1347.25 2193.24,1362 2227.83,1362 2266.33,1323.51 2266.33,1262.06 2321,1207.38 2321,1105 2343,1083 2449,1083 2516,1150 2516,1346 2605,1435 2605,1778 2698.65,1871.65 v1(2698.65,2000.96)
  Bottom Layer w15: v1(2177.11,1346.68) 2151.87,1321.44 C107.1@2151.87,1274.79 2178.42,1274.79 2201.5,1251.72 2201.5,1251.63 2209.09,1244.04 2209.09,951.73 2185.76,928.4 v1(2185.76,798.68)
3V3_LDO2: C97.1 C98.1 C117.1 C118.1 C119.1 J1.28 R1.2 R54.1 R55.1 R57.1 R72.1 TP7.1 U2.11 U8.1 U9.6 U10.2 U10.6 | length 1216.1
  Top Layer w10: v1(178.9,2245.61) 178.9,2245.49 188.33,2236.06 C118.1@188.33,2214.77 188.33,2195.33 180,2187 180,2152.71 U9.6@179.88,2152.59 ; R54.1@788.79,1790.23 809.51,1790.23 815.73,1784.01 v1(817.9,1784.01) ; U10.2@2960.42,2002.97 2960.42,1970.83 v1(2978.37,1952.88)
  Top Layer w11: U2.11@2014.49,976.67 2014.45,976.64 2014.45,917.88 2016.16,916.17
  Top Layer w12: R55.1@741.14,2149.43 741.14,2169.64 v1(757,2185.5) ; U8.1@890.73,2060.47 C117.1@890.73,2109.65 ; C117.1@891.14,2110.06 906.54,2110.06 912.36,2104.24 v1(913.98,2104.24) ; v1(1827.37,528.18) 1827.37,526.56 1833.72,520.21 R1.2@1833.72,491.94 TP7.1@1833.72,454.17 ; U10.6@3019.48,2176.2 C119.1@3019.5,2232.13
  Top Layer w15: v1(2596.11,2197.29) 2596.11,2198.11 2619.92,2221.92 R72.1@2619.92,2258.53 ; R57.1@2695.79,2104.58 2695.79,2077.97 v1(2709.3,2064.46) ; v1(3015.11,2254.97) 3015.11,2254.16 3019.12,2250.14 3019.12,2233.3 C119.1@3019.87,2232.55
  Top Layer w20: 2016.16,916.17 2016.16,893.04 2033.84,875.36 C98.1@2039.43,875.36 ; C97.1@2039.43,818.9 C98.1@2039.43,875.36 ; C98.1@2039.43,875.9 C98.1@2039.43,875.36
  L05_PWR1 w15: v1(2978.37,1952.88) 2977.8,1953.45 2977.8,1998.5 3041.84,2062.54 3041.84,2228.24 v1(3015.11,2254.97)
  Bottom Layer w12: J1.28@1818.33,408.19 1818.33,517.51 1827.37,526.56 v1(1827.37,528.18)
  other v1: 1827.1,546.63 2063.74,785.99 2063.74,804.91
5V0_LDO3: C99.1 C101.1 J1.34 R160.1 TP9.1 U2.15 | length 168.2
  Top Layer w12: v1(2500.58,903.21) 2500.58,901.59 2508.68,893.49 R160.1@2508.68,871.87
  Bottom Layer w12: v1(1738.69,533.15) 1738.69,492.77 1759.27,472.18 J1.34@1759.27,408.19
  other v1: 2086.92,932.77
15W_PD: J1.26 R42.2 R82.1 U14.3 | length 1088.5
  Top Layer w5.8: v1(1886.52,563.16) 1899.22,550.47 1932.12,550.47 1944.11,562.45 1973.72,562.45 1984.2,551.97 1984.2,471.12 2004.3,451.02 2109.72,451.02 2124.26,436.49 2124.26,385.06 2164.3,345.02 2194.52,345.02 2213.73,325.8 2213.73,138.65 2223.11,129.27 2282.21,129.27 2294.21,141.27 R82.1@2294.21,169.51 R42.2@2294.21,202.01 2294.21,218.19 2297.35,221.34 U14.3@2339.96,221.34
  Bottom Layer w5.8: J1.26@1838.01,408.19 1838.01,484.31 1856.2,502.5 1856.2,532.85 v1(1886.52,563.16)
+1V2: C74.1 L2.2 R29.2 R30.2 R43.3 U3.3 | length 344.4
  Top Layer w15: v1(1483.6,1894.75) 1484.17,1895.33 1521.58,1895.33 1532.02,1884.88 R30.2@1535.96,1884.88
  L05_PWR1 w15: v1(1483.6,1894.75) 1443.49,1854.64 1443.49,1739.07 v1(1524.95,1657.61)
+1V2_PG: R37.1 U3.1 U21.1 | length 2804.7
  Top Layer w5.8: v1(1489.31,1952.74) 1445.03,1908.47 1445.03,1856.97 1478.21,1823.79 1573.65,1823.79 1577.05,1827.18 R37.1@1577.05,1845.99 ; R37.1@1577.08,1846.01 1594.21,1846.01 1598.68,1841.55 1598.68,1826.1 1607.12,1817.66 U3.1@1629.45,1817.66
  L03_SIG1 w3.6: v1(2658.96,1778.17) 2620.25,1739.46 2620.25,1676.25 2579,1635 2579,1253 2688,1144 2688,923.54 2722,889.54 2722,832.06 v1(2693.2,803.26)
  L08_SIG2 w3.6: v1(1489.31,1952.74) 1542.01,2005.45 1686.32,2005.45 1749.51,1942.25 1775.85,1942.25 1780.55,1946.96 1856.77,1946.96 1898.41,1988.6 1998.85,1988.6 2073.05,1914.4 2210.65,1914.4 2311.87,1813.18 2395.21,1813.18 2409.12,1799.27 2643.15,1799.27 2650.15,1792.27 2650.15,1789.73 2658.96,1780.92 v1(2658.96,1778.17)
  Bottom Layer w5.8: v1(2693.2,803.26) 2704.61,814.68 U21.1@2733.62,814.68
ADC0_AIN0/DAC_OUT_MUX_SEL: U12.3 U20.1 U20.5 | length 2502.7
  Top Layer w5.8: v1(545.34,1939.06) 559.71,1924.7 U12.3@559.71,1900.61 ; U20.5@742.01,684.6 742.01,694.64 730.01,706.64 656.65,706.64 641.22,691.21 626.36,691.21 613.45,678.3 613.45,612.64 662.41,563.68 708.79,563.68 730.48,585.36 759.81,585.36 764.68,590.23 764.68,598.82 757.95,605.55 U20.1@742.31,605.55
  L03_SIG1 w3.6: v1(104.98,772.58) 104.98,808.3 134.52,837.85 134.52,1254.25 307.7,1427.43 307.7,1807.59 399.48,1899.37 467.46,1899.37 478.66,1910.57 490.92,1910.57 519.41,1939.06 v1(545.34,1939.06)
  L08_SIG2 w3.6: v1(104.98,772.58) 190.89,772.58 211.93,751.54 283.4,751.54 315.9,784.03 377.65,784.03 402.12,759.56 465.77,759.56 548.87,676.46 595.22,676.46 610.62,691.86 v1(641.87,691.86)
ADC_VREFHI_G0_G1: C126.2 C127.2 C128.2 S4.2 U1.V10 U1.V14 | length 1260.5
  Top Layer w10: C127.2@1066.4,975.23 1067,975.83 1067,989 1073,995 v1@1102.13,995 ; U1.V10@1072.63,1028.97 1101.02,1000.58 1101.02,996.11 v1@1102.13,995 ; v1(1102.55,994.58) v1@1102.13,995 ; C126.2@1166.59,910.2 1166.59,932.59 1176.43,942.43 C128.2@1176.43,965.15 1176.43,983.14 1182.29,989 1198.2,989 v1(1212.17,1002.97) ; U1.V14@1198.61,1028.97 1209.58,1018.01 1209.58,1007.73 1210.64,1006.67 v1@1210.64,1004.5 ; S4.2@1205.84,636.33 1217.48,636.33 1232.17,651.01 1232.17,656.98 v1(1243.78,668.59)
  L08_SIG2 w10: v1(1102.55,994.58) 1104.72,994.58 1111.95,987.34 1112.2,987.34 1128.75,970.79 1158.87,970.79 1191.05,1002.97 v1(1212.17,1002.97)
  Bottom Layer w8: v1(1212.17,1002.97) 1212.75,1002.97 1219.72,996.01 1275.95,996.01 1288.69,983.27 1337.05,983.27 1372.24,948.08 1372.24,916.85 1390.54,898.55 1443.06,898.55 1476.87,864.74 1476.87,822.63 1464.07,809.83 1435.37,809.83 1422.08,796.54 1422.08,791.61 1414.65,784.18 1379.82,784.18 1357.39,761.75 1357.39,735.92 1320.27,698.8 1320.27,657.69 1272.62,610.04 1236,610.04 1225.29,620.76 1225.29,650.1 v1(1243.78,668.59)
ADC_VREFHI_G2_G3: C123.2 C124.2 C125.2 R73.2 R239.1 S4.5 | length 772.5
  Top Layer w10: S4.5@1351.5,636.33 1313.85,636.33 1309.65,640.53 1309.65,667.17 1299.91,676.9 1299.91,796.05 1352.87,849.01 v1(1352.87,850.78)
  Bottom Layer w10: R73.2@1019.53,1043.74 1049.58,1043.74 1069.88,1023.45 1107.54,1023.45 1126.24,1004.75 1126.24,987.34 C124.2@1126.24,978.34 C125.2@1126.24,942.32 1126.24,926.15 1126.24,901.22 1138.05,889.41 C123.2@1167,889.41 1167,857.14 1173.6,850.53 1288.96,850.53 1289.53,851.09 R239.1@1335.03,851.09 ; R239.1@1335.6,850.53 1335.73,850.66 1352.74,850.66 v1(1352.87,850.78)
AM26x_ADC0_AIN0: U1.V15 U20.2 | length 799.8
  Top Layer w5.8: U20.2@742.01,625.54 864.66,625.54 904.98,665.86 904.98,712.54 931.6,739.16 1112.14,739.16 1146.02,773.04 1146.02,817.44 1250.17,921.59 1250.17,987.34 1250.17,997.98 1232.01,1016.14 1232.01,1027.07 U1.V15@1230.11,1028.97
AM26x_ADC0_AIN0/DAC_OUT: J1.119 U20.10 | length 708.9
  Top Layer w5.8: v1(677.92,592.73) 677.92,594.46 689.32,605.86 U20.10@709.14,605.86
  Bottom Layer w5.8: v1(677.92,592.73) 677.92,380.25 642.69,345.02 602.74,345.02 591.88,334.16 591.88,294.85 571.08,274.06 571.08,225.65 602.23,194.5 646.41,194.5 697.95,246.04 705.61,246.04 715.78,235.87 715.78,182.66 J1.119@715.85,182.59
AM26x_ADC0_AIN1: J1.117 U1.U15 | length 1487
  Top Layer w5.66: 1245.9,1022.47 1245.9,1035.48
  Top Layer w5.8: v1(675.78,322.62) 757.46,404.3 1191.73,404.3 1221.11,433.68 1221.11,480.51 1284.6,544 1284.6,634.38 1271.48,647.5 1271.48,667.52 1284.17,680.21 1284.17,788.11 1263.17,809.11 1263.17,987.34 1263.17,1003.37 1245.92,1020.61 1245.92,1022.45 ; U1.U15@1230.11,1060.47 1245.92,1044.66 1245.92,1035.5
  Bottom Layer w5.8: v1(675.78,322.62) 733.77,322.62 748.46,307.93 748.46,250.16 735.53,237.23 J1.117@735.53,182.59
AM26x_ADC0_AIN2_P: J1.120 U1.T14 | length 1391.7
  Top Layer w4.25: U1.T14@1198.61,1091.97 v1(1214.36,1076.22)
  L03_SIG1 w3.2: v1(1214.36,1076.22) 1214.36,1072.22 1246.51,1040.07 1246.51,1012.09 1271.25,987.34 1299.34,959.26 1299.34,926.84 1334.84,891.35 1334.84,824.26 1321.52,810.95 1321.52,794.53 1323.9,792.15 1326.55,792.15 v1(1338.39,803.99)
  Bottom Layer w4.25: J1.120@715.85,408.19 719.22,411.56 719.22,452.71 719.99,453.48 719.99,695.58 810.84,786.42 810.84,821.23 829.04,839.43 970.03,839.43 984.38,825.07 1199.66,825.07 1229.7,795.03 1326.63,795.03 1335.59,803.99 v1(1338.39,803.99)
AM26x_ADC0_AIN3_N: J1.118 U1.U14 | length 1391.4
  Top Layer w4.25: U1.U14@1198.61,1060.47 v1(1214.36,1044.72)
  L03_SIG1 w3.2: v1(1214.36,1044.72) 1214.8,1045.16 1226.29,1045.16 1235.81,1035.63 1235.81,1007.65 1256.12,987.34 1288.64,954.83 1288.64,922.41 1324.14,886.91 1324.14,874.11 1321.9,871.87 1318.38,871.87 1316.14,869.63 1316.14,862.91 1318.38,860.67 1321.9,860.67 1324.14,858.43 1324.14,851.71 1321.9,849.47 1318.38,849.47 1316.14,847.23 1316.14,840.51 1318.38,838.27 1321.9,838.27 1324.14,836.03 1324.14,832.53 1324.14,828.7 1310.82,815.38 1310.82,790.1 1323.06,777.86 1328.43,777.86 1337.98,768.31 v1(1338.39,768.31)
  Bottom Layer w4.25: J1.118@735.53,408.19 732.16,411.56 732.16,452.71 731.39,453.48 731.39,690.85 822.24,781.7 822.24,816.5 833.76,828.03 965.31,828.03 979.66,813.67 1194.94,813.67 1224.98,783.63 1239.83,783.63 1246.41,783.63 1330.69,783.63 1335.76,778.57 1335.76,770.94 v1(1338.39,768.31)
AM26x_ADC0_AIN4_P: J1.115 U1.U13 | length 1881.6
  Top Layer w4.25: U1.U13@1167.12,1060.47 1167.12,1060.39 1182.71,1044.8 v1(1182.71,1044.72)
  L03_SIG1 w3.2: v1(1182.71,1044.72) 1182.71,1041 1188.26,1035.45 1188.26,1031.4 1181.56,1024.7 1181.56,993.48 1201.36,973.68 1219.1,973.68 1251.09,941.69 1251.09,891.3 1271.62,870.76 1271.62,777.19 1287.3,761.52 1287.3,744.22 1324.96,706.56 1324.96,589.36 1324.96,586.5 1322.72,584.26 1319.2,584.26 1316.96,582.02 1316.96,575.3 1319.2,573.06 1322.72,573.06 1324.96,570.82 1324.96,564.1 1322.72,561.86 1319.2,561.86 1316.96,559.62 1316.96,552.9 1319.2,550.66 1322.72,550.66 1324.96,548.42 1324.96,541.7 1322.72,539.46 1319.2,539.46 1316.96,537.22 1316.96,530.5 1319.2,528.26 1322.72,528.26 1324.96,526.02 1324.96,524.42 1324.96,516.46 1280.72,472.22 1280.72,468.99 1278.48,466.75 1275.04,466.75 1272.8,464.51 1272.8,457.79 1275.04,455.55 1278.48,455.55 1280.72,453.31 1280.72,446.59 1278.48,444.35 1274.96,444.35 1272.72,442.11 1272.72,435.39 1274.96,433.15 1278.48,433.15 1280.72,430.91 1280.72,424.19 1278.48,421.95 1274.96,421.95 1272.72,419.71 1272.72,412.99 1274.96,410.75 1278.48,410.75 1280.72,408.51 1280.72,406.91 1280.72,396.08 1294.8,382 1321.97,382 1331.79,391.82 1331.79,411.94 1336.76,416.92 1343.9,416.92 v1(1346.73,419.75)
  Bottom Layer w4.25: J1.115@755.22,182.59 755.22,222.09 759.36,226.23 759.36,246.57 759.49,246.7 759.49,308.2 804.64,353.35 1066.45,353.35 1090.45,329.35 1329.35,329.35 1377.92,377.92 1377.92,451.07 1366.48,462.51 1346.43,462.51 1337.85,453.93 1337.85,429.09 1346.73,420.21 v1(1346.73,419.75)
AM26x_ADC0_AIN5_N: J1.113 U1.R14 | length 1881.4
  Top Layer w4.25: U1.R14@1198.61,1123.46 v1(1214.36,1107.71)
  L03_SIG1 w3.2: v1(1214.36,1107.71) 1198.55,1091.91 1198.55,1040.29 1198.96,1039.88 1198.96,1026.97 1192.26,1020.26 1192.26,997.91 1202.83,987.34 1205.79,984.38 1223.53,984.38 1261.79,946.12 1261.79,895.73 1282.32,875.19 1282.32,781.63 1298,765.95 1298,748.66 1335.66,710.99 1335.66,589.36 1335.66,512.03 1291.42,467.79 1291.42,400.51 1299.23,392.7 1317.54,392.7 1321.09,396.25 1321.09,410.24 1315.04,416.28 v1(1315.04,419.75)
  Bottom Layer w4.25: J1.113@774.9,182.59 774.9,222.09 770.76,226.23 770.76,241.85 770.89,241.98 770.89,303.48 809.36,341.95 1061.72,341.95 1085.73,317.95 1334.07,317.95 1389.32,373.2 1389.32,455.79 1371.2,473.91 1341.71,473.91 1326.45,458.65 1326.45,429.09 1317.11,419.75 v1(1315.04,419.75)
AM26x_ADC1_AIN0_P: J1.116 U1.T11 | length 1153.5
  Top Layer w4.25: U1.T11@1104.12,1091.97 v1(1119.83,1076.26)
  L03_SIG1 w3.2: v1@1119.87,1076.22 1104.02,1060.37 1104.02,1024.38 1079,999.36 1079,987.34 1079,954.01 1090.24,942.77 1100.31,932.7 1100.39,932.7 1146.09,887 1172.01,861.08 1172.01,788.81 1186.46,774.36 1186.46,759.68 1192.36,753.78 v1(1192.36,750.4)
  Bottom Layer w4.25: J1.116@755.22,408.19 758.59,411.56 758.59,452.71 759.36,453.48 759.36,624.06 846.86,711.56 991.89,711.56 1029.02,748.69 1105.92,748.69 1143.3,786.08 1172.02,786.08 1184.6,773.5 1184.6,759.77 1192.36,752.01 v1(1192.36,750.4)
AM26x_ADC1_AIN1_N: J1.114 U1.U11 | length 1147.4
  Top Layer w4.25: v1(1088.48,1044.83) U1.U11@1104.23,1060.57
  L03_SIG1 w3.2: v1@1089.06,1046.02 1089.06,1040.25 1093.32,1035.98 1093.32,1028.81 1068.3,1003.79 1068.3,949.58 1082.67,935.21 1083.8,934.08 1095.88,922 1095.96,922 1097.58,920.38 1097.58,917.21 1095.05,914.68 1095.05,911.51 1099.8,906.76 1102.97,906.76 1105.5,909.29 1108.67,909.29 1113.42,904.54 1113.42,901.37 1110.89,898.84 1110.89,895.67 1115.64,890.92 1118.81,890.92 1121.34,893.45 1124.51,893.45 1129.26,888.7 1129.26,885.53 1126.73,883 1126.73,879.83 1131.48,875.08 1134.65,875.08 1137.18,877.61 1140.35,877.61 1141.48,876.48 1157.03,860.93 1161.31,856.65 1161.31,850.37 1159.07,848.13 1155.55,848.13 1153.31,845.89 1153.31,839.17 1155.55,836.93 1159.07,836.93 1161.31,834.69 1161.31,827.97 1159.07,825.73 1155.55,825.73 1153.31,823.49 1153.31,816.77 1155.55,814.53 1159.07,814.53 1161.31,812.29 1161.31,805.55 1161.31,784.38 1175.76,769.93 1175.76,757.01 1169.15,750.4 v1(1165.5,750.4)
  Bottom Layer w4.25: J1.114@774.9,408.19 771.53,411.56 771.53,452.71 770.76,453.48 770.76,619.34 851.58,700.16 996.61,700.16 1033.74,737.29 1072.19,737.29 1086.56,737.29 1089.05,734.8 1089.05,732.5 1091.5,730.05 1098.85,730.05 1101.3,732.5 1101.3,734.8 1103.79,737.29 1110.64,737.29 1148.03,774.68 1167.3,774.68 1173.2,768.78 1173.2,759.77 1165.5,752.07 v1(1165.5,750.4)
AM26x_ADC1_AIN2_P: J1.111 U1.T12 | length 1619.9
  Top Layer w4.25: U1.T12@1135.62,1091.97 v1(1151.37,1076.22)
  L03_SIG1 w3.2: v1(1136.56,55.88) 1138.14,55.88 1146.06,63.81 1147.85,63.81 1150.83,63.82 1166.58,63.81 1180.2,77.43 1180.2,287.42 1246.87,354.09 1246.87,444.6 1246.87,541.8 1224.2,564.47 1224.2,849.77 1185.62,888.34 1185.62,909.49 1137.61,957.51 1128.75,966.37 1128.75,987.34 1128.75,1016.71 1135.73,1023.69 1135.73,1060.57 v1(1151.37,1076.22)
  Bottom Layer w4.25: J1.111@794.59,182.59 797.96,179.21 797.96,138.07 798.73,137.3 798.73,99.68 856.28,42.12 1076.55,42.12 1100.45,66.02 1126.41,66.02 v1(1136.56,55.88)
AM26x_ADC1_AIN3_N: J1.109 U1.V12 | length 1618.1
  Top Layer w4.25: v1(1120.08,1044.66) U1.V12@1135.83,1028.92
  L03_SIG1 w3.2: v1@1119.87,1044.72 1119.87,1040.72 1125.03,1035.56 1125.03,1028.12 1118.05,1021.15 1118.05,987.34 1118.05,961.94 1130.05,949.94 1131.18,948.81 1141.56,938.43 1141.56,935.26 1139.07,932.77 1139.07,929.6 1143.82,924.85 1146.99,924.85 1149.48,927.34 1152.65,927.34 1157.4,922.59 1157.4,919.42 1154.91,916.93 1154.91,913.76 1159.66,909.01 1162.83,909.01 1165.32,911.5 1168.49,911.5 1169.62,910.37 1174.92,905.06 1174.92,883.91 1213.5,845.33 1213.5,721.53 1213.5,708.73 1211.26,706.49 1207.74,706.49 1205.5,704.25 1205.5,697.53 1207.74,695.29 1211.26,695.29 1213.5,693.05 1213.5,686.33 1211.26,684.09 1207.74,684.09 1205.5,681.85 1205.5,675.13 1207.74,672.89 1211.26,672.89 1213.5,670.65 1213.5,664.62 1213.5,560.04 1236.17,537.36 1236.17,486.17 1236.17,484.28 1233.93,482.04 1230.41,482.04 1228.17,479.8 1228.17,473.08 1230.41,470.84 1233.93,470.84 1236.17,468.6 1236.17,461.88 1233.93,459.64 1230.41,459.64 1228.17,457.4 1228.17,450.68 1230.41,448.44 1233.93,448.44 1236.17,446.2 1236.17,444.6 1236.17,358.52 1169.5,291.85 1169.5,81.86 1162.15,74.51 1155.27,74.51 1142.75,74.52 1139.39,77.88 1139.39,84.73 v1(1136.56,87.57)
  Bottom Layer w4.25: J1.109@814.27,182.59 810.9,179.21 810.9,138.07 810.13,137.3 810.13,104.4 861,53.52 1071.83,53.52 1095.73,77.42 1126.41,77.42 v1(1136.56,87.57)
